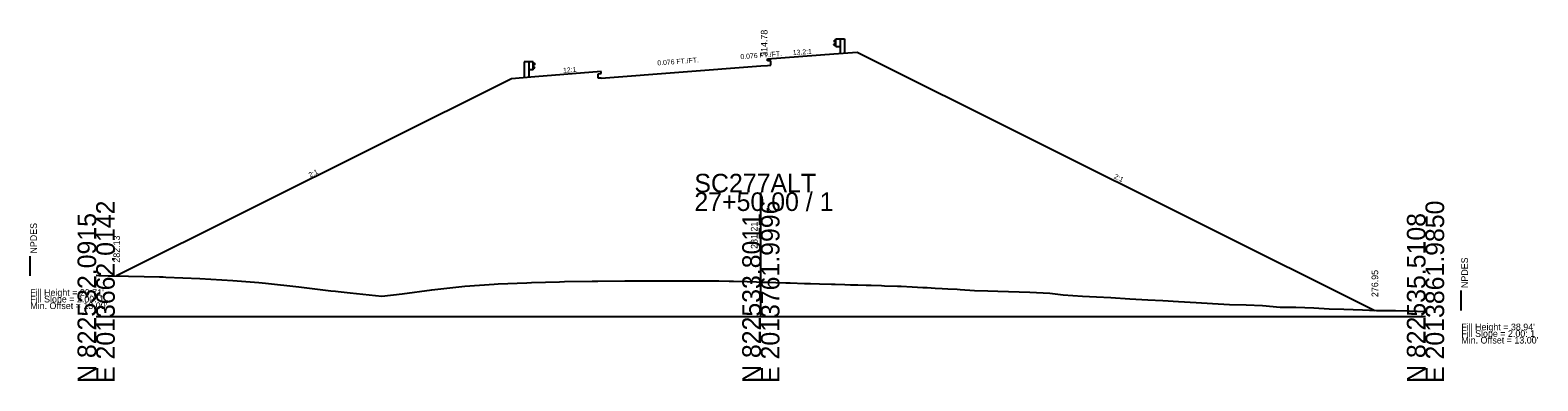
# Model space of a CAD drawing. Extents: x 205929 to 2357175, y -1785700 to 827636.
# Drawn here: x 2017410.2 to 2017637.1, y 825534.6 to 825587.4 of the extents above; entities that cross this region are included whole.
import ezdxf

# ---------------------------------------------------------------- set-up
doc = ezdxf.new("R2010")
doc.units = 0
for name, color, linetype in [('RD_GPK_XS_Cell', 7, 'Continuous'), ('RD_XS_Base', 7, 'Continuous'), ('RD_XS_EarthShd', 7, 'Continuous'), ('RD_XS_ExGround', 7, 'Continuous'), ('RD_XS_GR', 7, 'Continuous'), ('RD_XS_NPDES', 7, 'Continuous'), ('RD_XS_Pave', 7, 'Continuous'), ('RD_XS_TieSlope', 7, 'Continuous'), ('RD_XS_TX_Elev_EX', 7, 'Continuous'), ('RD_XS_TX_Elev_PR', 7, 'Continuous'), ('RD_XS_TX_ShdSlope', 7, 'Continuous'), ('RD_XS_TX_Slope', 7, 'Continuous'), ('RD_XS_TX_Warning', 7, 'Continuous')]:
    doc.layers.add(name, color=color, linetype=linetype)

msp = doc.modelspace()

# ---------------------------------------------------------------- linework, layer by layer
at = {"layer": 'RD_GPK_XS_Cell'}
for p, q in [((2017520.17, 825544.26), (2017520.17, 825562.98)), ((2017420.17, 825544.26), (2017520.17, 825544.26)), ((2017520.17, 825544.26), (2017620.17, 825544.26))]:
    msp.add_line(p, q, dxfattribs=at)
at = {"layer": 'RD_XS_Base'}
for p, q in [((2017496.17, 825580.22), (2017520.17, 825582.04)), ((2017520.17, 825582.04), (2017521.17, 825582.12))]:
    msp.add_line(p, q, dxfattribs=at)
at = {"layer": 'RD_XS_EarthShd'}
for p, q in [((2017521.17, 825583.12), (2017531.17, 825583.87)), ((2017531.17, 825583.87), (2017534.67, 825584.14)), ((2017496.17, 825581.22), (2017486.17, 825580.39)), ((2017486.17, 825580.39), (2017482.67, 825580.1))]:
    msp.add_line(p, q, dxfattribs=at)
at = {"layer": 'RD_XS_ExGround'}
msp.add_lwpolyline([(2017420.17, 825550.5), (2017420.58, 825550.47), (2017420.9, 825550.46), (2017421.95, 825550.42), (2017422.74, 825550.4), (2017429.68, 825550.24), (2017430.27, 825550.23), (2017430.64, 825550.22), (2017435.79, 825549.98), (2017440.71, 825549.72), (2017444.65, 825549.39), (2017445.64, 825549.31), (2017450.64, 825548.72), (2017455.46, 825548.14), (2017456.17, 825548.07), (2017456.57, 825548.03), (2017458.39, 825547.82), (2017463.17, 825547.32), (2017466.19, 825547.71), (2017470.65, 825548.31), (2017471.1, 825548.34), (2017475.65, 825548.82), (2017480.04, 825549.16), (2017480.65, 825549.19), (2017484.96, 825549.37), (2017485.65, 825549.39), (2017489.88, 825549.51), (2017490.65, 825549.53), (2017494.79, 825549.6), (2017495.65, 825549.61), (2017499.71, 825549.64), (2017500.65, 825549.64), (2017502.18, 825549.63), (2017502.65, 825549.63), (2017503.42, 825549.64), (2017504.85, 825549.64), (2017508.99, 825549.66), (2017510.17, 825549.66), (2017511.77, 825549.65), (2017512.81, 825549.64), (2017513.84, 825549.63), (2017515.38, 825549.62), (2017516.06, 825549.6), (2017518.1, 825549.53), (2017519.53, 825549.48), (2017520.27, 825549.46), (2017521.31, 825549.43), (2017522.43, 825549.4), (2017523.93, 825549.35), (2017524.58, 825549.34), (2017526.75, 825549.27), (2017527.66, 825549.24), (2017529.01, 825549.2), (2017530.81, 825549.15), (2017531.34, 825549.13), (2017532.79, 825549.09), (2017533.67, 825549.06), (2017534.78, 825549.03), (2017536.01, 825548.99), (2017536.78, 825548.97), (2017538.33, 825548.93), (2017538.76, 825548.91), (2017540.75, 825548.85), (2017541.27, 825548.83), (2017542.94, 825548.74), (2017544.53, 825548.66), (2017545.2, 825548.62), (2017546.41, 825548.55), (2017547.46, 825548.49), (2017548.28, 825548.44), (2017549.72, 825548.37), (2017550.16, 825548.35), (2017552.33, 825548.21), (2017554.31, 825548.14), (2017555.82, 825548.08), (2017560.66, 825547.96), (2017563.63, 825547.79), (2017565.66, 825547.56), (2017568.54, 825547.33), (2017570.66, 825547.24), (2017572.85, 825547.12), (2017575.66, 825546.95), (2017578.38, 825546.79), (2017580.66, 825546.66), (2017583.03, 825546.53), (2017585.66, 825546.37), (2017588.12, 825546.22), (2017590.66, 825546.09), (2017593.2, 825546.04), (2017595.66, 825545.91), (2017598.29, 825545.7), (2017600.66, 825545.68), (2017603.38, 825545.6), (2017605.67, 825545.41), (2017607.88, 825545.39), (2017610.67, 825545.3), (2017612.79, 825545.19), (2017615.67, 825545.16), (2017617.71, 825545.13), (2017620.17, 825545.04)], dxfattribs=at)
at = {"layer": 'RD_XS_GR'}
for p, q in [((2017531.44, 825586.05), (2017531.17, 825585.85)), ((2017531.17, 825585.85), (2017531.17, 825585.8)), ((2017531.17, 825585.8), (2017531.44, 825585.6)), ((2017531.17, 825585.28), (2017531.44, 825585.48)), ((2017531.17, 825585.23), (2017531.17, 825585.28)), ((2017531.44, 825585.03), (2017531.17, 825585.23)), ((2017531.44, 825584.96), (2017531.44, 825586.12)), ((2017531.44, 825586.12), (2017532.11, 825586.12)), ((2017532.11, 825586.12), (2017532.11, 825583.95)), ((2017532.11, 825586.12), (2017532.78, 825586.12)), ((2017532.78, 825586.12), (2017532.78, 825584)), ((2017531.44, 825584.96), (2017532.11, 825584.96)), ((2017484.57, 825582.64), (2017484.57, 825580.25)), ((2017485.24, 825582.64), (2017484.57, 825582.64)), ((2017485.24, 825582.64), (2017485.24, 825580.31)), ((2017485.9, 825582.64), (2017485.24, 825582.64)), ((2017485.9, 825581.47), (2017485.24, 825581.47)), ((2017485.9, 825581.47), (2017485.9, 825582.64)), ((2017485.9, 825582.56), (2017486.17, 825582.36)), ((2017486.17, 825582.31), (2017485.9, 825582.11)), ((2017486.17, 825581.79), (2017485.9, 825581.99)), ((2017485.9, 825581.54), (2017486.17, 825581.74)), ((2017486.17, 825582.36), (2017486.17, 825582.31)), ((2017486.17, 825581.74), (2017486.17, 825581.79))]:
    msp.add_line(p, q, dxfattribs=at)
at = {"layer": 'RD_XS_NPDES'}
for p, q in [((2017410.25, 825550.39), (2017410.25, 825553.39)), ((2017625.55, 825545.2), (2017625.55, 825548.2))]:
    msp.add_line(p, q, dxfattribs=at)
at = {"layer": 'RD_XS_Pave'}
for p, q in [((2017521.17, 825582.79), (2017521.17, 825583.12)), ((2017521.67, 825582.82), (2017521.17, 825582.79)), ((2017521.67, 825582.15), (2017521.67, 825582.82)), ((2017495.67, 825580.85), (2017496.17, 825580.89)), ((2017495.67, 825580.18), (2017495.67, 825580.85)), ((2017496.17, 825580.89), (2017496.17, 825581.22)), ((2017521.17, 825582.12), (2017521.67, 825582.15)), ((2017496.17, 825580.22), (2017495.67, 825580.18))]:
    msp.add_line(p, q, dxfattribs=at)
at = {"layer": 'RD_XS_TieSlope'}
for p, q in [((2017534.67, 825584.14), (2017612.55, 825545.2)), ((2017482.67, 825580.1), (2017423.25, 825550.39))]:
    msp.add_line(p, q, dxfattribs=at)

# ---------------------------------------------------------------- texts
at = {"layer": 'RD_GPK_XS_Cell'}
for s, p in [('SC277ALT', (2017510.17, 825562.98)), ('27+50.00 / 1', (2017510.17, 825560.18))]:
    msp.add_text(s, height=2.8, dxfattribs=at).set_placement(p)
for s, p in [('E 2013662.0142', (2017422.97, 825534.26)), ('E 2013761.9996', (2017522.97, 825534.26)), ('E 2013861.9850', (2017622.97, 825534.26)), ('N 822532.0915', (2017420.17, 825534.26)), ('N 822533.8011', (2017520.17, 825534.26)), ('N 822535.5108', (2017620.17, 825534.26))]:
    msp.add_text(s, height=2.8, rotation=90, dxfattribs=at).set_placement(p)
at = {"layer": 'RD_XS_TX_Elev_EX'}
msp.add_text('281.21', height=1, rotation=90, dxfattribs=at).set_placement((2017519.67, 825554.47))
at = {"layer": 'RD_XS_TX_Elev_PR'}
for s, p in [(' 314.78', (2017521.17, 825583.04)), ('282.13', (2017423.75, 825552.39)), ('276.95', (2017613.05, 825547.2))]:
    msp.add_text(s, height=1, rotation=90, dxfattribs=at).set_placement(p)
at = {"layer": 'RD_XS_TX_ShdSlope'}
for s, rotation, p in [('13.2:1', 4.3347, (2017525, 825583.66)), ('12:1', 4.7636, (2017490.44, 825580.99))]:
    msp.add_text(s, height=0.75, rotation=rotation, dxfattribs=at).set_placement(p)
at = {"layer": 'RD_XS_TX_Slope'}
for s, rotation, p in [('0.076 FT./FT.', 4.3347, (2017504.62, 825582.11)), ('0.076 FT./FT.', 4.3347, (2017517.12, 825583.06)), ('2:1', 26.5651, (2017452.35, 825565.21)), ('2:1', 333.4349, (2017573.22, 825565.15))]:
    msp.add_text(s, height=0.75, rotation=rotation, dxfattribs=at).set_placement(p)
at = {"layer": 'RD_XS_TX_Warning'}
for p in [(2017411.25, 825553.39), (2017626.55, 825548.2)]:
    msp.add_text(' NPDES', height=1, rotation=90, dxfattribs=at).set_placement(p)
for s, p in [("Fill Height = 29.71' ", (2017410.25, 825547.39)), ('Fill Slope = 2.00: 1', (2017410.25, 825546.39)), ("Min. Offset = 13.00' ", (2017410.25, 825545.39)), ("Fill Height = 38.94' ", (2017625.55, 825542.2)), ('Fill Slope = 2.00: 1', (2017625.55, 825541.2)), ("Min. Offset = 13.00' ", (2017625.55, 825540.2))]:
    msp.add_text(s, height=1, dxfattribs=at).set_placement(p)

doc.saveas('drawing.dxf')
